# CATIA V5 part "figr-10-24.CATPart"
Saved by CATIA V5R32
Part number: Part1
Bounding box of the stored display mesh (mm): x -180.516 to 0, y -36.805 to 65.824, z 0 to 36.805
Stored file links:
  D:\PROJECTS\Project 2022\CATIA V5 6R 2022\Resources\Part Files\c10_catia_v5_6r2022_prt\c10_catia_v5_6r2022_prt\figr-10-24.CATPart
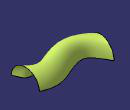
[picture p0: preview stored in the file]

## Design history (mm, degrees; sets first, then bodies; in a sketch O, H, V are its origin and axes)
Set1
  Sweep1: type Unspec, Profile Sketch2, Guide Sketch1
Body1 (main body)
  Sketch1 on xy-plane, origin (0, 0, 0), H (1, 0, 0), V (0, 1, 0)
    spline S1 through (0, 0) (-31.5913, 14.7273) (-94.8038, 0) (-174.5181, 29.5113)
    point P1 (0, 0)
    point P2 (-94.8038, 0)
    coincidence: P1 O, P2 H
  Sketch2 on yz-plane, origin (0, 0, 0), H (0, 1, 0), V (0, 0, 1)
    arc A1 centre (0, 0) radius 36.8048 from (36.8048, 0) to (-36.8048, 0) ccw
    point P1 (-36.8048, 0)
    point P2 (36.8048, 0)
    coincidence: P1 H, P2 H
